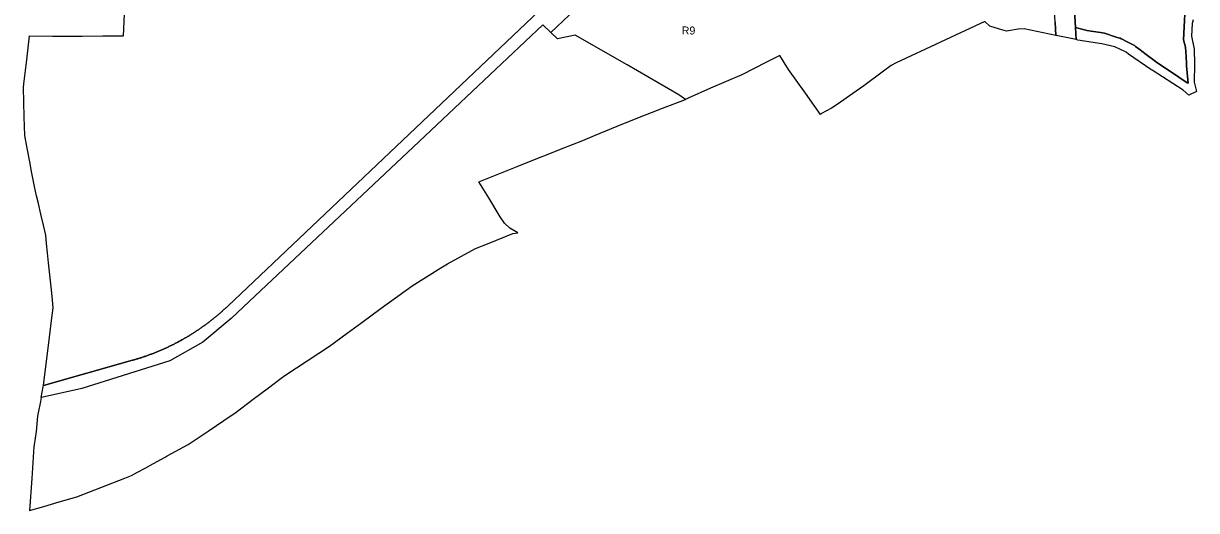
# Model space of a CAD drawing. Extents: x 7439486 to 7443435, y 5551288 to 5554556.
# Drawn here: x 7439486 to 7440952, y 5551288 to 5551897 of the extents above; entities that cross this region are included whole.
import ezdxf

# ---------------------------------------------------------------- set-up
doc = ezdxf.new("R2010")
doc.units = 0
for name, color, linetype in [('#Ruszcza', 7, 'Continuous'), ('linie_rozgraniczajace', 7, 'Continuous'), ('oznaczenia_przeznaczen', 7, 'Continuous')]:
    doc.layers.add(name, color=color, linetype=linetype)

msp = doc.modelspace()

# ---------------------------------------------------------------- linework, layer by layer
at = {"layer": '#Ruszcza'}
for points in [[(7440135.19, 5551895.51), (7439980.48, 5551749.71), (7439944.8, 5551716.11), (7439775.75, 5551556.78), (7439745.56, 5551528.32), (7439710.48, 5551498.7), (7439669.24, 5551475.48), (7439559.17, 5551441.06), (7439508.57, 5551429.54), (7439508.41, 5551429.48), (7439508.4, 5551429.48)], [(7440313.28, 5551802.25), (7440305.28, 5551808.23), (7440240.44, 5551845.47), (7440175.61, 5551882.71), (7440153.47, 5551878.03), (7440145.09, 5551886.05), (7440135.19, 5551895.51)], [(7439493.84, 5551288.34), (7439511.69, 5551293.55), (7439530.77, 5551299.12), (7439553, 5551305.6), (7439613.07, 5551328.98), (7439621.12, 5551332.12), (7439628.85, 5551336.37), (7439638.16, 5551341.49), (7439648.67, 5551347.27), (7439663.08, 5551355.19), (7439665.63, 5551356.6), (7439692.02, 5551371.11), (7439716.93, 5551387.71), (7439747.12, 5551407.84), (7439750.32, 5551410.24), (7439773.22, 5551427.42), (7439792.2, 5551441.65), (7439808.42, 5551453.82), (7439812.66, 5551457), (7439827.27, 5551466.57), (7439868.54, 5551493.69), (7439890.66, 5551509.95), (7439908.89, 5551523.35), (7439933.14, 5551541.17), (7439971.79, 5551569.26), (7440007.68, 5551591.64), (7440015.98, 5551596.82), (7440051.03, 5551615.78), (7440068.08, 5551622.73), (7440097.78, 5551634.85), (7440103.93, 5551635.7), (7440094.04, 5551641.2), (7440087.28, 5551647.72), (7440081.95, 5551655.46), (7440067.73, 5551679.1), (7440055.02, 5551699.35), (7440103.29, 5551718.66), (7440124.64, 5551727.37), (7440145.84, 5551735.64), (7440159.25, 5551740.88), (7440172.46, 5551746.05), (7440185.34, 5551750.87), (7440199.78, 5551757.16), (7440228.25, 5551768.89), (7440256.12, 5551779.97), (7440270.84, 5551785.86), (7440284.55, 5551791.33), (7440313.28, 5551802.25)], [(7440313.28, 5551802.25), (7440313.28, 5551802.25)], [(7439508.4, 5551429.48), (7439507.45, 5551424.59), (7439504.74, 5551410.66)], [(7439504.74, 5551410.66), (7439503.88, 5551406.28), (7439502.06, 5551387.04), (7439499.56, 5551370.7), (7439499.21, 5551368.43), (7439496.52, 5551328.38), (7439493.84, 5551288.34)]]:
    msp.add_lwpolyline(points, dxfattribs=at)
at = {"layer": 'linie_rozgraniczajace'}
msp.add_lwpolyline([(7440774.18, 5551920.04), (7440781.88, 5552072.73), (7440806.89, 5552072.31), (7440803.64, 5552007.76), (7440799.21, 5551920.11), (7440800.76, 5551892.23), (7440801.61, 5551877.02), (7440776.82, 5551882.03), (7440776.29, 5551882.14), (7440775.35, 5551899.06)], close=True, dxfattribs=at)
for points in [[(7439711.83, 5551519.34), (7439712.69, 5551519.97), (7439713.55, 5551520.6), (7439714.41, 5551521.23), (7439715.27, 5551521.87), (7439716.13, 5551522.51), (7439716.98, 5551523.15), (7439717.83, 5551523.79), (7439718.68, 5551524.44), (7439719.52, 5551525.09), (7439720.37, 5551525.75), (7439721.21, 5551526.41), (7439722.05, 5551527.07), (7439722.88, 5551527.73), (7439723.71, 5551528.4), (7439724.54, 5551529.07), (7439725.37, 5551529.74), (7439726.2, 5551530.42), (7439727.02, 5551531.1), (7439727.84, 5551531.79), (7439728.66, 5551532.47), (7439729.47, 5551533.16), (7439730.29, 5551533.85), (7439731.1, 5551534.55), (7439731.9, 5551535.25), (7439732.71, 5551535.95), (7439733.51, 5551536.65), (7439734.31, 5551537.36), (7439735.11, 5551538.07), (7439735.9, 5551538.78), (7439736.69, 5551539.5), (7439737.48, 5551540.22), (7439738.27, 5551540.94), (7439739.05, 5551541.67), (7439739.83, 5551542.39), (7439740.61, 5551543.13), (7439741.39, 5551543.86), (7440170.49, 5551951.58)], [(7440170.49, 5551951.58), (7439741.39, 5551543.86), (7439740.61, 5551543.13), (7439739.83, 5551542.39), (7439739.05, 5551541.67), (7439738.27, 5551540.94), (7439737.48, 5551540.22), (7439736.69, 5551539.5), (7439735.9, 5551538.78), (7439735.11, 5551538.07), (7439734.31, 5551537.36), (7439733.51, 5551536.65), (7439732.71, 5551535.95), (7439731.9, 5551535.25), (7439731.1, 5551534.55), (7439730.29, 5551533.85), (7439729.47, 5551533.16), (7439728.66, 5551532.47), (7439727.84, 5551531.79), (7439727.02, 5551531.1), (7439726.2, 5551530.42), (7439725.37, 5551529.74), (7439724.54, 5551529.07), (7439723.71, 5551528.4), (7439722.88, 5551527.73), (7439722.05, 5551527.07), (7439721.21, 5551526.41), (7439720.37, 5551525.75), (7439719.52, 5551525.09), (7439718.68, 5551524.44), (7439717.83, 5551523.79), (7439716.98, 5551523.15)], [(7439487.87, 5551757.21), (7439487.23, 5551780.67), (7439486.73, 5551798.99), (7439486.22, 5551817.3), (7439486.73, 5551821.61), (7439490.28, 5551851.69), (7439493.83, 5551881.78), (7439522.57, 5551881.56), (7439551.31, 5551881.34), (7439559.42, 5551881.42), (7439585.41, 5551881.67), (7439611.4, 5551881.93), (7439613.43, 5551927.75)], [(7440191.16, 5551929.83), (7440145.09, 5551886.05), (7440135.19, 5551895.51), (7439980.48, 5551749.71), (7439944.8, 5551716.11), (7439775.75, 5551556.78), (7439745.56, 5551528.32), (7439710.48, 5551498.7), (7439669.24, 5551475.48), (7439559.17, 5551441.06), (7439508.57, 5551429.54)], [(7440145.09, 5551886.05), (7440191.16, 5551929.83)], [(7440937.85, 5551917.06), (7440936.43, 5551892.9), (7440935.72, 5551876.86), (7440938.27, 5551867.69), (7440938.98, 5551855.82), (7440939.54, 5551846.61), (7440939.54, 5551844.49), (7440941.17, 5551826.77), (7440941.37, 5551822.45), (7440940.44, 5551823.06), (7440929.83, 5551830.07), (7440914.28, 5551840.49), (7440902.49, 5551848.36), (7440898.58, 5551851.43), (7440889.2, 5551858.46), (7440883.77, 5551862.63), (7440881.6, 5551864.25), (7440875.86, 5551868.53), (7440874.53, 5551869.66), (7440873.51, 5551870.22), (7440864.47, 5551874.78), (7440858.95, 5551877.49), (7440857.95, 5551878.08), (7440856.66, 5551878.75), (7440854.53, 5551879.43), (7440851.72, 5551880.33), (7440836.98, 5551885.23), (7440832.19, 5551885.96), (7440820.53, 5551887.77), (7440814.95, 5551888.63), (7440813.74, 5551888.82), (7440810.51, 5551889.71), (7440800.76, 5551892.23), (7440799.21, 5551920.11)], [(7440947.8, 5551901.92), (7440946.49, 5551897.2), (7440945.8, 5551881.58), (7440949.18, 5551865.04), (7440949.44, 5551846.27), (7440949.15, 5551823.96), (7440952.02, 5551812.25), (7440942.4, 5551807.61), (7440935.22, 5551813.99), (7440896.65, 5551839.08), (7440894.79, 5551839.85), (7440867.03, 5551858.89), (7440863.91, 5551861.43), (7440849.93, 5551868.07), (7440833.85, 5551871.89), (7440803.85, 5551876.57), (7440801.61, 5551877.02), (7440800.76, 5551892.23), (7440810.51, 5551889.71), (7440813.74, 5551888.82), (7440814.95, 5551888.63), (7440820.53, 5551887.77), (7440832.19, 5551885.96), (7440836.98, 5551885.23), (7440851.72, 5551880.33), (7440854.53, 5551879.43), (7440856.66, 5551878.75), (7440857.95, 5551878.08), (7440858.95, 5551877.49), (7440864.47, 5551874.78), (7440873.51, 5551870.22), (7440874.53, 5551869.66), (7440875.86, 5551868.53), (7440881.6, 5551864.25), (7440883.77, 5551862.63), (7440889.2, 5551858.46), (7440898.58, 5551851.43), (7440902.49, 5551848.36), (7440914.28, 5551840.49), (7440929.83, 5551830.07), (7440940.44, 5551823.06), (7440941.37, 5551822.45), (7440941.17, 5551826.77), (7440939.54, 5551844.49), (7440939.54, 5551846.61), (7440938.98, 5551855.82), (7440938.27, 5551867.69), (7440935.72, 5551876.86), (7440936.43, 5551892.9), (7440937.85, 5551917.06)], [(7440687.6, 5551899.74), (7440576.88, 5551847.95), (7440570.46, 5551844.73), (7440559.03, 5551836.19), (7440537.89, 5551820.37), (7440536.48, 5551819.4), (7440522.51, 5551809.6), (7440502.79, 5551795.9), (7440495.98, 5551791.31), (7440483.56, 5551784.53), (7440482.16, 5551783.6), (7440463.4, 5551810.24), (7440442.26, 5551839.67)], [(7440775.35, 5551899.06), (7440776.29, 5551882.14), (7440736.68, 5551890.71), (7440729.04, 5551890.03), (7440714.45, 5551887.79), (7440705.78, 5551890.12), (7440693.75, 5551894.06), (7440687.6, 5551899.74)], [(7440442.26, 5551839.67), (7440431.17, 5551857.11), (7440414.56, 5551848.75), (7440399.06, 5551840.81), (7440384.02, 5551833.13), (7440344.84, 5551816.42), (7440316.83, 5551803.84), (7440314.23, 5551802.61), (7440313.29, 5551802.25), (7440305.28, 5551808.23), (7440240.44, 5551845.47), (7440175.61, 5551882.71), (7440153.47, 5551878.03), (7440145.09, 5551886.05)], [(7439622.91, 5551476.3), (7439622.49, 5551476.19), (7439511.26, 5551444.8), (7439518.77, 5551505.17), (7439521.75, 5551529.36), (7439523.27, 5551541.74), (7439522.83, 5551546.28), (7439522.31, 5551551.62), (7439520.71, 5551568.08), (7439519.57, 5551579.27), (7439517.6, 5551598.21), (7439516.34, 5551610.41), (7439515.13, 5551622.21), (7439514.08, 5551632.52), (7439511.19, 5551644.92), (7439507.97, 5551658.81), (7439504.82, 5551672.32), (7439502.58, 5551681.92), (7439499.93, 5551693.34), (7439496.38, 5551712.14), (7439494.09, 5551724.26), (7439490.9, 5551741.18), (7439487.87, 5551757.21)], [(7439508.41, 5551429.5), (7439511.02, 5551442.9), (7439511.26, 5551444.79), (7439511.26, 5551444.8), (7439622.49, 5551476.19), (7439622.91, 5551476.3), (7439623.93, 5551476.6), (7439624.96, 5551476.89), (7439625.98, 5551477.2), (7439627.01, 5551477.5), (7439628.03, 5551477.81), (7439629.05, 5551478.12), (7439630.07, 5551478.44), (7439631.09, 5551478.76), (7439632.11, 5551479.08), (7439633.12, 5551479.41), (7439634.14, 5551479.74), (7439635.15, 5551480.08), (7439636.16, 5551480.42), (7439637.17, 5551480.76), (7439638.18, 5551481.11), (7439639.19, 5551481.46), (7439640.2, 5551481.81), (7439641.2, 5551482.17), (7439642.21, 5551482.53), (7439643.21, 5551482.9), (7439644.21, 5551483.27), (7439645.21, 5551483.64), (7439646.21, 5551484.02), (7439647.21, 5551484.4), (7439648.2, 5551484.78), (7439649.2, 5551485.17), (7439650.19, 5551485.56), (7439651.18, 5551485.96), (7439652.17, 5551486.36), (7439653.16, 5551486.76), (7439654.15, 5551487.17), (7439655.14, 5551487.58), (7439656.12, 5551487.99), (7439657.1, 5551488.41), (7439658.08, 5551488.83), (7439659.06, 5551489.26), (7439660.04, 5551489.69), (7439661.02, 5551490.12), (7439661.99, 5551490.55), (7439662.96, 5551490.99), (7439663.93, 5551491.44), (7439664.9, 5551491.88), (7439665.87, 5551492.33), (7439666.84, 5551492.79), (7439667.8, 5551493.25), (7439668.77, 5551493.71), (7439669.73, 5551494.17), (7439670.69, 5551494.64), (7439671.64, 5551495.11), (7439672.6, 5551495.59), (7439673.55, 5551496.07), (7439674.51, 5551496.55), (7439675.46, 5551497.04), (7439676.4, 5551497.53), (7439677.35, 5551498.02), (7439678.3, 5551498.52), (7439679.24, 5551499.02), (7439680.18, 5551499.53), (7439681.12, 5551500.03), (7439682.05, 5551500.55), (7439682.99, 5551501.06), (7439683.92, 5551501.58), (7439684.85, 5551502.1), (7439685.78, 5551502.63), (7439686.71, 5551503.15), (7439687.64, 5551503.69), (7439688.56, 5551504.22), (7439689.48, 5551504.76), (7439690.4, 5551505.3), (7439691.32, 5551505.85), (7439692.24, 5551506.4), (7439693.15, 5551506.95), (7439694.06, 5551507.51), (7439694.97, 5551508.07), (7439695.88, 5551508.63), (7439696.78, 5551509.2), (7439697.68, 5551509.77), (7439698.58, 5551510.34), (7439699.48, 5551510.92), (7439700.38, 5551511.5), (7439701.27, 5551512.08), (7439702.16, 5551512.67), (7439703.05, 5551513.26), (7439703.94, 5551513.85), (7439704.83, 5551514.45), (7439705.71, 5551515.05), (7439706.59, 5551515.65), (7439707.47, 5551516.26), (7439708.35, 5551516.87), (7439709.22, 5551517.48), (7439710.09, 5551518.1), (7439710.96, 5551518.72), (7439711.83, 5551519.34)], [(7439716.98, 5551523.15), (7439716.13, 5551522.51), (7439715.27, 5551521.87), (7439714.41, 5551521.23), (7439713.55, 5551520.6), (7439712.69, 5551519.97), (7439711.83, 5551519.34), (7439710.96, 5551518.72), (7439710.09, 5551518.1), (7439709.22, 5551517.48), (7439708.35, 5551516.87), (7439707.47, 5551516.26), (7439706.59, 5551515.65), (7439705.71, 5551515.05), (7439704.83, 5551514.45), (7439703.94, 5551513.85), (7439703.05, 5551513.26), (7439702.16, 5551512.67), (7439701.27, 5551512.08), (7439700.38, 5551511.5), (7439699.48, 5551510.92), (7439698.58, 5551510.34), (7439697.68, 5551509.77), (7439696.78, 5551509.2), (7439695.88, 5551508.63), (7439694.97, 5551508.07), (7439694.06, 5551507.51), (7439693.15, 5551506.95), (7439692.24, 5551506.4), (7439691.32, 5551505.85), (7439690.4, 5551505.3), (7439689.48, 5551504.76), (7439688.56, 5551504.22), (7439687.64, 5551503.69), (7439686.71, 5551503.15), (7439685.78, 5551502.63), (7439684.85, 5551502.1), (7439683.92, 5551501.58), (7439682.99, 5551501.06), (7439682.05, 5551500.55), (7439681.12, 5551500.03), (7439680.18, 5551499.53), (7439679.24, 5551499.02), (7439678.3, 5551498.52), (7439677.35, 5551498.02), (7439676.4, 5551497.53), (7439675.46, 5551497.04), (7439674.51, 5551496.55), (7439673.55, 5551496.07), (7439672.6, 5551495.59), (7439671.64, 5551495.11), (7439670.69, 5551494.64), (7439669.73, 5551494.17), (7439668.77, 5551493.71), (7439667.8, 5551493.25), (7439666.84, 5551492.79), (7439665.87, 5551492.33), (7439664.9, 5551491.88), (7439663.93, 5551491.44), (7439662.96, 5551490.99), (7439661.99, 5551490.55), (7439661.02, 5551490.12), (7439660.04, 5551489.69), (7439659.06, 5551489.26), (7439658.08, 5551488.83), (7439657.1, 5551488.41), (7439656.12, 5551487.99), (7439655.14, 5551487.58), (7439654.15, 5551487.17), (7439653.16, 5551486.76), (7439652.17, 5551486.36), (7439651.18, 5551485.96), (7439650.19, 5551485.56), (7439649.2, 5551485.17), (7439648.2, 5551484.78), (7439647.21, 5551484.4), (7439646.21, 5551484.02), (7439645.21, 5551483.64), (7439644.21, 5551483.27), (7439643.21, 5551482.9), (7439642.21, 5551482.53), (7439641.2, 5551482.17), (7439640.2, 5551481.81), (7439639.19, 5551481.46), (7439638.18, 5551481.11), (7439637.17, 5551480.76), (7439636.16, 5551480.42), (7439635.15, 5551480.08), (7439634.14, 5551479.74), (7439633.12, 5551479.41), (7439632.11, 5551479.08), (7439631.09, 5551478.76), (7439630.07, 5551478.44), (7439629.05, 5551478.12), (7439628.03, 5551477.81), (7439627.01, 5551477.5), (7439625.98, 5551477.2), (7439624.96, 5551476.89), (7439623.93, 5551476.6), (7439622.91, 5551476.3)]]:
    msp.add_lwpolyline(points, dxfattribs=at)

# ---------------------------------------------------------------- texts
at = {"layer": 'oznaczenia_przeznaczen'}
msp.add_text('R9', height=10, dxfattribs=at).set_placement((7440308.69, 5551883.49))

doc.saveas('drawing.dxf')
